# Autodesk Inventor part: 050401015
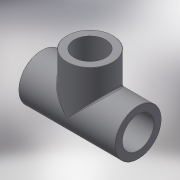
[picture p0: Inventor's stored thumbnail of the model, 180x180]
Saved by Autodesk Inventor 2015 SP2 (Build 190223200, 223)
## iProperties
Created: 2017-10
Part Number: 050401015
Material: Generic
Description: PLASSON THREADED TEE PVC 1.1/2"
Document SubType Name: Modeling
Designer: KIM
Density: 1 g/cm^3
Appearance: Default
Author: KIM
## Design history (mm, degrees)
derived "050401.ipt"
feature "Solid1::050401.ipt"
feature "Solid2::050401.ipt"
tag "TaggingFeature1"
body "Solid1"
other parameters: "d0" = 118, "d1" = 62, "d2" = 22, "d4" = 44.845, "d5" = 40.3605, "d7" = 0.44845, "d8" = 22, "d9" = 59, "d10" = 62, "d15" = 0, "d18" = 44.845, "d24" = 0.44845, "d30" = 44.845, "d31" = 22, "d32" = 0, "d33" = 40.3605, "d35" = 0, "d36" = 2.24225, "G_" = 44.845, "E_" = 62, "H_" = 118, "lt_" = 22
